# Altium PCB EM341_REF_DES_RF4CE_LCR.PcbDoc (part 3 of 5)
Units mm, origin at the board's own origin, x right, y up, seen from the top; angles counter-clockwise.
Board outline 218.38 x 83.13 mm, 2 copper layers (Top Layer, Carbon Ink Layer); 111 components, 91 nets, 369 pads, 80 vias.
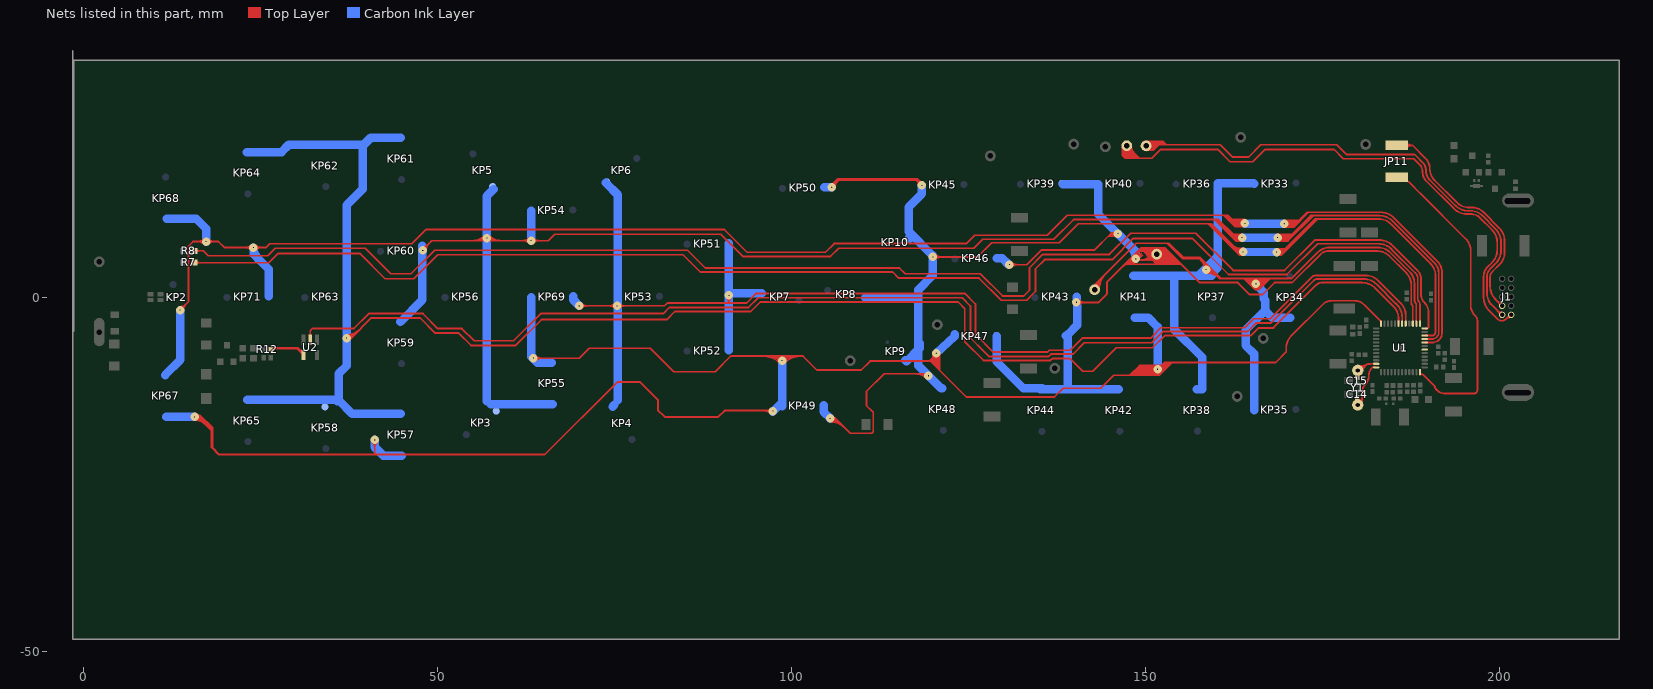
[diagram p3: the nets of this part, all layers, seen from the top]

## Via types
v1: diameter 1.2, hole 0, Top Layer to Carbon Ink Layer, 80 vias

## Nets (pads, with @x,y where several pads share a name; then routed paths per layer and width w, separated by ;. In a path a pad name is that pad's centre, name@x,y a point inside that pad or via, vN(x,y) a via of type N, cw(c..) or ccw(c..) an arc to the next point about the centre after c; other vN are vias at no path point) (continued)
NetR12_2: R12.2 U2.4 | length 20.1
  Top Layer w0.254: R12.2@26.35,-7.275 26.465,-7.16 30.28,-7.16 31.13,-8.01 U2.4@31.13,-8.29 ; R12.2@26.417,-7.403 26.527,-7.403 26.527,-7.623 26.85,-7.3 ; U2.4@30.81,-7.93 30.18,-7.3 26.85,-7.3 ; U2.4@30.931,-8.256 U2.4@30.95,-8.275 ; U2.4@31.023,-8.173 U2.4@31.05,-8.2 ; R12.2@26.557,-7.493 cw(c27.023,-7.959) 27.023,-7.3 ccw(c27.023,-7.959) R12.2@26.557,-7.493 ; R12.2@26.557,-7.493 cw(c27.361,-8.297) 27.361,-7.16 ccw(c27.361,-8.297) R12.2@26.557,-7.493 ; R12.2@26.557,-7.213 ccw(c26.767,-7.003) 26.767,-7.3 ; R12.2@26.557,-7.213 ccw(c26.767,-7.003) 26.767,-7.3 ; R12.2@26.557,-7.213 ccw(c26.767,-7.003) 26.767,-7.3 ; R12.2@26.557,-7.213 ccw(c26.767,-7.003) 26.767,-7.3 ; 26.85,-7.3 ccw(c26.85,-7.601) 26.589,-7.451 cw(c26.85,-7.601) 26.85,-7.3 ; R12.2@26.377,-7.313 cw(c26.748,-7.684) 26.748,-7.16 ccw(c26.748,-7.684) R12.2@26.377,-7.313 ; 30.399,-7.519 ccw(c30.751,-7.166) 30.985,-7.606 cw(c30.751,-7.166) 30.399,-7.519 ; 30.465,-7.345 ccw(c31.054,-6.756) 31.054,-7.589 cw(c31.054,-6.756) 30.465,-7.345 ; 30.641,-7.761 ccw(c30.919,-7.483) 31.104,-7.831 cw(c30.919,-7.483) 30.641,-7.761 ; U2.4@30.884,-8.004 ccw(c31.088,-7.801) 31.223,-8.055 cw(c31.088,-7.801) U2.4@30.884,-8.004
NRESET: JP11.1 U1.12 | length 43.7
  Top Layer w0.254: JP11.1@185.42,16.93 185.44,16.95 cw(c185.482,16.907) JP11.1@185.482,16.967 ; JP11.1@186.672,16.412 cw(c186.672,15.644) 187.215,16.187 188.777,14.625 ; U1.12@188.703,-10.6 188.703,-10.811 ccw(c188.769,-10.811) 188.722,-10.857 188.73,-10.865 cw(c188.73,-11.698) 189.319,-11.109 189.32,-11.11 ; 188.766,14.639 195.143,8.262 cw(c193.347,6.466) 195.887,6.466 195.887,5.201 ; 189.315,-11.111 190.787,-12.582 cw(c190.638,-12.731) 190.848,-12.731 ; 190.85,-12.73 ccw(c191.224,-12.73) 190.96,-12.995 191.109,-13.144 ccw(c192.283,-11.97) 192.283,-13.63 194.686,-13.63 ; 194.677,-13.633 196.335,-13.633 ccw(c196.335,-13.18) 196.655,-13.5 ccw(c196.183,-13.028) 196.85,-13.028 196.85,-3.902 ; 195.887,5.155 195.887,-1.183 ccw(c197.904,-1.183) 196.477,-2.61 cw(c195.578,-3.509) 196.85,-3.509 196.85,-4.09
NRESET_1: J1.8 JP11.2 | length 42.4
  Top Layer w0.254: JP11.2@185.42,21.43 187.655,21.43 189.486,19.599 ; JP11.2@185.542,21.452 cw(c185.542,19.592) JP11.2@186.857,20.907 ; 188.921,20.164 189.486,19.599 ; J1.8@200.315,-1.245 199.365,-0.295 cw(c201.161,1.501) 198.621,1.501 198.621,2.806 cw(c199.761,2.806) 198.955,3.613 199.996,4.654 ccw(c198.37,6.28) 200.67,6.28 200.67,7.927 ccw(c198.13,7.927) 199.926,9.723 197.633,12.017 ccw(c196.125,10.509) 196.125,12.641 195.692,12.641 cw(c195.692,15.181) 193.896,13.385 190.762,16.519 cw(c192.348,18.105) 190.105,18.105 ccw(c187.993,18.105) 189.486,19.599 ; 187.633,21.43 cw(c187.633,22.693) 186.74,21.8 ccw(c187.633,22.693) 187.633,21.43 ; 187.633,21.43 ccw(c187.633,20.167) 186.74,21.06 cw(c187.633,20.167) 187.633,21.43 ; 199.764,-0.694 cw(c199.212,-1.245) J1.8@199.992,-1.245 ; 199.764,-0.694 ccw(c200.315,-0.142) J1.8@200.315,-0.922 ; 199.764,-0.694 cw(c199.212,-1.245) J1.8@199.992,-1.245 ; 199.764,-0.694 ccw(c200.315,-0.142) J1.8@200.315,-0.922 ; 199.764,-0.694 ccw(c200.315,-0.142) J1.8@200.315,-0.922 ; 199.764,-0.694 cw(c199.212,-1.245) J1.8@199.992,-1.245
OSCA: C14.1 U1.48 Y1.1 | length 10.2
  Top Layer w0.254: C14.1@179.842,-14.16 cw(c179.561,-14.442) 179.959,-14.442 Y1.1@179.959,-15.226 ; Y1.1@180.069,-14.57 ccw(c180.176,-14.06) 180.626,-14.321 ccw(c181.334,-14.729) Y1.1@180.564,-15.003 ; U1.48@182.528,-9.925 182.089,-9.925 ccw(c182.089,-10.121) 181.95,-9.983 181.914,-10.018 ccw(c182.939,-11.043) 181.49,-11.043 181.49,-11.094 cw(c179.689,-11.094) 180.962,-12.367 ccw(c181.788,-13.193) 180.62,-13.193 180.62,-14.113 cw(c179.531,-14.113) 180.301,-14.884 Y1.1@179.959,-15.226 ; Y1.1@179.959,-15.226 179.959,-15.274 cw(c179.993,-15.24) 179.945,-15.24 Y1.1@179.959,-15.226 ; C14.1@179.735,-14.332 cw(c179.195,-14.873) 179.959,-14.873 ccw(c179.195,-14.873) C14.1@179.735,-14.332
OSCB: C15.1 U1.47 Y1.2 | length 7
  Top Layer w0.254: Y1.2@179.88,-10.709 cw(c179.987,-10.709) 179.911,-10.634 ccw(c178.389,-10.496) 179.917,-10.496 179.917,-10.348 180.096,-10.169 cw(c181.892,-11.965) 181.892,-9.425 U1.47@182.528,-9.425 ; Y1.2@179.905,-10.33 ccw(c179.857,-10.282) Y1.2@179.925,-10.282 ; Y1.2@180.038,-9.947 ccw(c180.234,-9.218) 180.611,-9.871 ; Y1.2@180.104,-9.702 ccw(c180.458,-8.38) 181.142,-9.565 ; Y1.2@180.343,-10.422 cw(c181.278,-10.582) 180.804,-9.76 ; Y1.2@180.593,-10.465 cw(c181.971,-10.7) 181.272,-9.49
PA0: KP3.2 KP5.2 KP54.1 KP55.1 KP56.1 KP59.1 KP60.1 | length 205.6
  Top Layer w0.254: v1@47.78,6.59 49.146,7.956 65.596,7.956 66.51,8.87 89.96,8.87 93.09,5.74 105.47,5.74 106.63,6.9 125.69,6.9 126.96,8.17 137.02,8.17 139.8,10.95 160.27,10.95 162.35,8.87 163.63,8.87 ; v1@47.9,7.063 ccw(c47.9,7.915) 48.503,7.313 ; v1@48.119,6.59 cw(c48.937,6.59) 48.359,7.169 ; v1@48.373,6.59 cw(c49.805,6.59) 48.792,7.602 ; 54.939,7.956 ccw(c54.939,10.341) v1@56.626,8.654 ; 55.553,7.956 ccw(c55.553,9.727) v1@56.805,8.475 ; 56.166,7.956 ccw(c56.166,9.114) v1@56.985,8.295 ; v1@56.935,8.295 ccw(c57.754,9.114) 57.754,7.956 ; v1@56.96,7.956 v1(56.96,8.32) ; v1@57.115,8.475 ccw(c58.367,9.727) 58.367,7.956 ; v1@57.294,8.654 ccw(c58.981,10.341) 58.981,7.956 ; 62.014,7.956 ccw(c62.014,9.146) v1@62.856,8.304 ; 62.082,7.956 cw(c62.082,6.862) v1@62.856,7.636 ; v1@63.524,7.636 cw(c64.298,6.862) 64.298,7.956 ; v1@63.524,8.304 ccw(c64.366,9.146) 64.366,7.956 ; 159.72,10.92 162.709,7.931 163.319,7.931 ; 160.09,10.83 162.679,8.241 ; 162.31,8.5 163.59,8.5 ; 162.34,8.65 163.62,8.65 ; 162.35,8.36 163.63,8.36 ; 162.67,8.2 163.64,8.2 ; 162.76,8.05 163.72,8.02
  Carbon Ink Layer w1.2: KP59.1@44.73,-3.51 47.826,-0.414 47.826,7.24 ; KP60.1@47.826,6.436 KP60.1@47.88,6.49 ; 56.936,-14.73 56.936,14.252 KP5.2@57.926,15.242 ; 57.494,-15.156 KP55.1@66.24,-15.156 ; v1@63.184,7.97 KP54.1@63.184,12.17
  other v1: 47.9,6.59 63.19,7.97
PA0_1: U1.21 | length 111.6
  Top Layer w0.254: v1@168.57,7.92 170.08,7.92 ; v1@168.58,8.87 170.64,8.87 ; v1@168.6,8.37 170.37,8.37 173.498,11.498 183.024,11.498 cw(c183.024,8.958) 184.82,10.754 190.827,4.746 cw(c189.541,3.46) 191.36,3.46 ; v1(168.6,8.4) 168.6,8.2 170.24,8.2 ; v1@168.806,8.676 170.676,8.676 ; v1@168.86,8.03 170.12,8.03 ; 170.47,8.48 169.25,8.48 ; 174.81,11.498 173.267,11.498 170.64,8.87 ; 175.24,11.498 173.658,11.498 170.08,7.92 ; U1.21@189.378,-5.925 190.436,-5.925 ccw(c190.436,-5.029) 191.07,-5.662 ccw(c190.357,-4.949) 191.366,-4.949 191.366,3.47 ; v1@168.755,8.245 cw(c169.794,7.206) 169.794,8.676 ccw(c169.794,7.206) v1@168.755,8.245 ; v1@168.755,8.245 cw(c169.322,7.678) 169.322,8.48 ccw(c169.322,7.678) v1@168.755,8.245 ; v1@168.755,8.555 ccw(c169.201,9.001) 169.201,8.37 cw(c169.201,9.001) v1@168.755,8.555 ; v1@168.755,8.555 ccw(c169.612,9.412) 169.612,8.2 cw(c169.612,9.412) v1@168.755,8.555 ; v1@168.934,8.066 cw(c170.407,6.593) 170.407,8.676 ccw(c170.407,6.593) v1@168.934,8.066 ; v1@168.934,8.066 cw(c169.935,7.065) 169.935,8.48 ccw(c169.935,7.065) v1@168.934,8.066 ; v1@168.934,8.066 cw(c169.669,7.331) 169.669,8.37 ccw(c169.669,7.331) v1@168.934,8.066 ; v1@168.934,8.066 cw(c169.259,7.741) 169.259,8.2 ccw(c169.259,7.741) v1@168.934,8.066 ; v1@168.934,8.734 ccw(c169.549,9.349) 169.549,8.48 cw(c169.549,9.349) v1@168.934,8.734 ; v1@168.934,8.734 ccw(c169.814,9.614) 169.814,8.37 cw(c169.814,9.614) v1@168.934,8.734 ; v1@168.934,8.734 ccw(c170.225,10.025) 170.225,8.2 cw(c170.225,10.025) v1@168.934,8.734 ; 169.25,8.48 cw(c169.25,8.741) 169.019,8.62 ccw(c169.25,8.741) 169.25,8.48 ; 169.25,8.48 ccw(c169.25,8.295) 169.067,8.324 cw(c169.25,8.295) 169.25,8.48 ; 170.08,7.92 cw(c170.08,9.073) 169.031,8.596 ccw(c170.08,9.073) 170.08,7.92 ; 170.12,8.03 cw(c170.12,9.349) 169.001,8.65 ccw(c170.12,9.349) 170.12,8.03 ; 170.64,8.87 ccw(c170.64,6.665) 168.96,8.094 cw(c170.64,6.665) 170.64,8.87 ; v1@168.38,8.587 cw(c168.992,8.067) 168.992,8.87 ccw(c168.992,8.067) v1@168.38,8.587 ; v1@168.568,8.386 ccw(c169.291,8.714) 169.291,7.92 cw(c169.291,8.714) v1@168.568,8.386 ; v1@168.57,8.381 ccw(c169.204,8.777) 169.204,8.03 cw(c169.204,8.777) v1@168.57,8.381 ; v1@168.573,8.423 cw(c169.541,7.6) 169.541,8.87 ccw(c169.541,7.6) v1@168.573,8.423 ; v1@168.575,8.425 cw(c169.181,7.819) 169.181,8.676 ccw(c169.181,7.819) v1@168.575,8.425 ; v1@168.767,8.258 cw(c170.09,7.132) 170.09,8.87 ccw(c170.09,7.132) v1@168.767,8.258 ; v1@168.786,8.516 ccw(c169.662,9.063) 169.662,8.03 cw(c169.662,9.063) v1@168.786,8.516 ; v1@168.799,8.491 ccw(c169.686,8.893) 169.686,7.92 cw(c169.686,8.893) v1@168.799,8.491
  Carbon Ink Layer w1.2: v1@163.6,8.396 v1@168.599,8.373
  other v1: 163.6,8.4
PA1: 
PA1_1: KP8.2 KP9.2 KP10.1 KP45.1 KP48.1 KP49.1 KP50.1 U1.22 | length 313.8
  Top Layer w0.254: v1(105.43,-17.14) 106.15,-17.14 ; v1@118.3,16.12 117.76,16.66 106.43,16.66 ; v1@118.394,15.68 117.588,16.489 106.65,16.507 v1(105.65,15.51) 105.65,15.88 106.43,16.66 ; v1(119.3,-11.12) 119.02,-10.84 113.05,-10.84 110.55,-13.34 110.55,-15.31 111.52,-16.28 111.52,-19 111.29,-19.23 108.24,-19.23 106.15,-17.14 ; v1(119.93,5.66) 126.21,5.66 128.22,7.67 137.75,7.67 140.44,10.36 159.23,10.36 162.78,6.81 ; v1@120.264,5.326 cw(c121.072,4.518) 121.072,5.66 cw(c121.072,6.802) v1@120.264,5.994 ; 158.82,10.36 163.28,5.9 v1@163.76,5.9 ; 159.045,10.305 163.33,6.02 163.33,5.9 ; 163.089,6.184 ccw(c163.75,6.844) v1@163.75,5.91 ; 163.129,6.184 ccw(c163.79,6.844) v1@163.79,5.91 ; v1@163.69,6.81 162.78,6.81 ; v1(163.74,6.37) 163.02,6.37 ; v1@163.78,6.63 162.94,6.63 ; v1@168.38,6.48 169.44,6.48 ; v1@168.46,5.89 169.11,5.89 174.255,11.035 ; v1(168.47,6.36) 169.36,6.36 ; v1@168.53,6.09 169.18,6.09 ; v1@168.57,6.81 169.69,6.81 ; v1@168.62,6.64 169.62,6.64 ; v1@168.63,6.26 169.36,6.26 ; 174.035,11.035 169.36,6.36 ; U1.22@189.378,-5.425 190.511,-5.425 ccw(c190.511,-5.103) 190.738,-5.331 ccw(c190.32,-4.913) 190.912,-4.913 190.912,2.335 ; 190.907,2.3 190.907,2.972 ccw(c188.367,2.972) 190.164,4.768 184.643,10.288 ccw(c182.847,8.492) 182.847,11.032 180.848,11.032 176.923,11.035 173.915,11.035 169.69,6.81 ; 106.15,-17.14 cw(c106.15,-16.829) 105.864,-16.952 ccw(c106.15,-16.829) 106.15,-17.14 ; 106.15,-17.14 ccw(c106.15,-17.451) 105.864,-17.328 cw(c106.15,-17.451) 106.15,-17.14 ; 106.43,16.66 ccw(c107.252,15.838) 106.113,15.605 cw(c107.252,15.838) 106.43,16.66 ; 106.459,16.316 cw(c105.653,17.125) 105.651,15.983 ccw(c105.653,17.125) 106.459,16.316 ; 106.459,16.316 ccw(c107.265,15.507) 106.123,15.509 cw(c107.265,15.507) 106.459,16.316 ; 162.78,6.81 cw(c162.78,6.322) 163.268,6.346 ccw(c162.78,6.322) 162.78,6.81 ; 162.94,6.63 cw(c162.94,6.3) 163.269,6.329 ccw(c162.94,6.3) 162.94,6.63 ; 163.02,6.37 cw(c163.02,6.059) 163.306,6.182 ccw(c163.02,6.059) 163.02,6.37 ; 163.02,6.37 ccw(c163.02,6.681) 163.306,6.558 cw(c163.02,6.681) 163.02,6.37 ; v1@163.74,6.081 cw(c163.74,7.629) 162.646,6.534 ccw(c163.74,7.629) v1@163.74,6.081 ; v1@163.74,6.081 cw(c163.74,7.218) 162.936,6.414 ccw(c163.74,7.218) v1@163.74,6.081 ; v1@163.74,6.335 cw(c163.74,8.496) 162.212,6.968 ccw(c163.74,8.496) v1@163.74,6.335 ; v1@163.74,6.335 cw(c163.74,8.085) 162.502,6.848 ccw(c163.74,8.085) v1@163.74,6.335 ; v1@163.74,6.589 cw(c163.74,9.363) 161.779,7.401 ccw(c163.74,9.363) v1@163.74,6.589 ; v1@163.74,6.589 cw(c163.74,8.953) 162.069,7.281 ccw(c163.74,8.953) v1@163.74,6.589 ; v1@163.74,6.843 cw(c163.74,10.23) 161.345,7.835 ccw(c163.74,10.23) v1@163.74,6.843 ; v1@163.74,6.843 cw(c163.74,9.82) 161.635,7.715 ccw(c163.74,9.82) v1@163.74,6.843 ; 169.36,6.26 cw(c169.36,6.765) 168.901,6.556 ccw(c169.36,6.765) 169.36,6.26 ; 169.36,6.26 ccw(c169.36,5.485) 168.807,6.028 cw(c169.36,5.485) 169.36,6.26 ; 169.36,6.36 cw(c169.36,6.961) 168.862,6.625 ccw(c169.36,6.961) 169.36,6.36 ; 169.36,6.36 ccw(c169.36,5.759) 168.862,6.095 cw(c169.36,5.759) 169.36,6.36 ; 169.44,6.48 ccw(c169.44,5.863) 168.891,6.144 cw(c169.44,5.863) 169.44,6.48 ; 169.62,6.64 ccw(c169.62,5.859) 168.904,6.171 cw(c169.62,5.859) 169.62,6.64 ; 169.69,6.81 ccw(c169.69,6.015) 168.925,6.231 cw(c169.69,6.015) 169.69,6.81 ; v1@105.406,-17.114 cw(c105.765,-17.5) 106.138,-17.128 ccw(c105.765,-17.5) v1@105.406,-17.114 ; v1@105.43,-17.613 cw(c105.43,-20.493) 107.467,-18.457 ccw(c105.43,-20.493) v1@105.43,-17.613 ; v1@105.43,-17.359 cw(c105.43,-19.626) 107.033,-18.023 ccw(c105.43,-19.626) v1@105.43,-17.359 ; v1@105.43,-17.105 cw(c105.43,-18.759) 106.599,-17.589 ccw(c105.43,-18.759) v1@105.43,-17.105 ; v1@105.43,-16.851 cw(c105.43,-17.892) 106.166,-17.156 ccw(c105.43,-17.892) v1@105.43,-16.851 ; v1@105.579,-17.3 cw(c105.945,-17.693) 106.324,-17.314 ccw(c105.945,-17.693) v1@105.579,-17.3 ; v1@105.752,-17.486 cw(c106.124,-17.886) 106.51,-17.5 ccw(c106.124,-17.886) v1@105.752,-17.486 ; v1@105.865,15.554 cw(c106.698,15.725) 106.096,16.326 ccw(c106.698,15.725) v1@105.865,15.554 ; 117.482,-10.84 cw(c117.482,-12.938) 118.966,-11.454 ccw(c117.482,-12.938) 117.482,-10.84 ; 117.637,16.439 ccw(c118.147,16.947) 118.296,16.243 cw(c118.147,16.947) 117.637,16.439 ; 117.658,16.418 cw(c117.02,15.782) 117.921,15.781 ccw(c117.02,15.782) 117.658,16.418 ; 117.982,16.438 cw(c117.484,15.94) 118.178,15.818 ccw(c117.484,15.94) 117.982,16.438 ; 118.007,16.413 ccw(c118.394,16.8) 118.394,16.253 cw(c118.394,16.8) 118.007,16.413 ; 118.095,-10.84 cw(c118.095,-12.325) 119.145,-11.275 ccw(c118.095,-12.325) 118.095,-10.84 ; 118.709,-10.84 cw(c118.709,-11.711) 119.325,-11.095 ccw(c118.709,-11.711) 118.709,-10.84 ; 163.047,6.81 cw(c163.047,6.335) 163.521,6.359 ccw(c163.047,6.335) 163.047,6.81 ; 163.314,6.81 cw(c163.314,6.349) 163.775,6.372 ccw(c163.314,6.349) 163.314,6.81 ; v1@168.436,6.37 cw(c169.019,6.205) 169.019,6.81 ccw(c169.019,6.205) v1@168.436,6.37 ; v1@168.671,6.273 cw(c169.232,6.028) 169.232,6.64 ccw(c169.232,6.028) v1@168.671,6.273 ; v1@168.681,6.3 cw(c169.354,6.11) 169.354,6.81 ccw(c169.354,6.11) v1@168.681,6.3 ; v1@168.804,6.694 ccw(c169.322,7.212) 169.322,6.48 cw(c169.322,7.212) v1@168.804,6.694
  Carbon Ink Layer w1.2: KP49.1@104.536,-15.28 104.5,-15.316 104.5,-16.21 v1@105.46,-17.17 ; KP50.1@104.586,15.48 105.58,15.48 105.59,15.49 v1(105.65,15.51) ; KP8.2@110.356,-0.086 117.824,-0.086 117.89,-0.02 ; KP9.2@116.035,-8.91 116.205,-9.08 116.21,-9.08 118.06,-7.23 118.06,-6.5 ; KP10.1@116.538,8.155 116.62,8.237 116.62,8.46 ; v1(118.394,15.78) 118.394,14.584 116.52,12.71 116.52,9.24 119.87,5.89 119.89,5.91 119.89,3.04 117.89,1.04 117.89,-9.7 121.104,-12.914 KP48.1@121.27,-12.914 ; 120.32,-12.13 120.344,-12.154 ; v1(163.74,6.37) v1@168.46,6.36
PA2: R8.1 U1.24 | length 200.3
  Top Layer w0.254: R8.1@15.65,6.53 16.91,6.53 17.62,5.82 25.98,5.82 27.06,6.9 39.76,6.9 43.36,3.3 46.24,3.3 49.56,6.62 85.28,6.62 87.8,4.1 115.21,4.1 116.01,3.3 126.63,3.3 129.78,0.15 132.76,0.15 133.58,0.97 133.58,4.15 135.45,6.02 144.86,6.02 147.86,9.02 157.07,9.02 162.32,3.77 169.59,3.77 173.869,8.049 183.003,8.049 cw(c183.003,5.509) 184.799,7.305 188.404,3.7 cw(c187.31,2.605) 188.857,2.605 188.857,0.386 ccw(c190.458,0.386) 189.326,-0.746 cw(c187.851,-2.222) 189.937,-2.222 189.937,-4.161 cw(c189.656,-4.161) 189.855,-4.36 cw(c189.698,-4.203) 189.698,-4.425 U1.24@189.378,-4.425 ; R8.1@15.857,6.323 cw(c16.355,5.825) 16.355,6.53 cw(c16.355,7.235) R8.1@15.857,6.737
PA2_1: 
PA3: R7.1 U1.25 | length 197.8
  Top Layer w0.254: R7.1@15.78,4.83 26.15,4.83 27.49,6.17 38.97,6.17 42.56,2.58 46.6,2.58 50,5.98 84.65,5.98 87.09,3.54 114.25,3.54 115.11,2.68 126.44,2.68 129.58,-0.46 133.17,-0.46 134.42,0.79 134.42,4 135.71,5.29 145.25,5.29 148.24,8.28 156.58,8.28 161.68,3.18 169.93,3.18 174.268,7.518 182.892,7.518 cw(c182.892,4.978) 184.688,6.774 188.066,3.396 cw(c187.251,2.581) 188.403,2.581 188.403,-0.279 ccw(c188.904,-0.279) 188.55,-0.633 cw(c188.18,-1.003) 188.703,-1.003 U1.25@188.703,-3.75 ; R7.1@15.857,4.673 cw(c16.234,4.296) 16.234,4.83 ; R7.1@15.857,5.087 ccw(c16.476,5.706) 16.476,4.83
PA3_1: 
PA4: KP33.2 KP34.1 KP35.1 KP36.2 KP37.1 KP38.1 KP41.1 pad.4 U1.26 | length 288.3
  Top Layer w0.254: pad.4@142.44,1.05 142.44,1.39 143.608,2.558 ; pad.4@142.9,0.94 142.9,1.85 148.66,7.61 ; pad.4@143.04,1.2 143.04,1.99 ; pad.4@143.26,1.34 143.26,2.03 ; pad.4@143.41,0.94 143.41,2.36 ; 149.81,7.61 148.66,7.61 ; 150.96,7.61 153.05,7.61 155.23,5.43 157.59,5.43 160.39,2.63 161.23,2.63 ; 163.82,2.63 165.37,1.08 ; 164.38,2.2 164.38,2.48 ; 164.6,1.97 164.6,2.48 ; 164.81,1.89 164.81,2.48 ; 164.94,1.66 164.94,2.48 ; v1@165.07,1.53 165.07,2.48 ; v1@165.24,1.42 165.24,2.48 ; v1@165.331,1.456 cw(c165.153,1.079) 165.57,1.079 ; v1@165.331,1.457 cw(c165.153,1.08) 165.57,1.08 ; v1@165.37,1.54 165.37,1.08 ; 165.371,1.09 cw(c165.744,1.064) 165.651,1.426 ccw(c165.744,1.064) 165.372,1.1 ; v1@165.455,1.417 cw(c165.393,1.046) 165.768,1.08 ; v1@165.455,1.451 cw(c165.393,1.08) 165.77,1.08 v1@165.77,1.5 ; v1@165.47,1.43 165.47,2.48 ; v1(165.533,1.884) 165.74,2.61 ; v1@165.57,1.6 165.57,1.08 ; v1@165.61,1.52 165.61,2.48 ; v1@165.85,1.41 165.85,2.48 ; 165.91,1.31 165.91,2.63 ; 166.05,1.24 166.05,1.46 ; 166.07,1.47 166.07,2.48 ; 166.2,1.41 166.2,2.48 ; 166.36,1.49 166.36,2.63 ; 166.48,1.74 166.48,2.48 ; 166.55,1.74 166.55,2.48 ; 166.66,1.877 166.66,2.48 ; 166.8,2 166.8,2.48 ; 166.92,2.2 166.92,2.48 ; 167.05,2.275 167.05,2.48 ; 167.56,2.63 166.01,1.08 165.37,1.08 ; 187.932,1.97 ccw(c185.719,1.97) 187.284,3.536 184.559,6.261 ccw(c182.762,4.465) 182.762,7.005 175.934,7.005 ccw(c175.934,4.683) 174.293,6.325 170.598,2.63 160.62,2.63 157.65,5.6 155.26,5.6 153.25,7.61 148.66,7.61 ; 187.949,1.97 187.949,-0.448 ccw(c188.56,-0.448) 188.128,-0.879 cw(c187.947,-1.061) 188.203,-1.061 U1.26@188.203,-3.75 ; 143.04,1.99 cw(c142.724,1.99) 142.739,1.674 ccw(c142.724,1.99) 143.04,1.99 ; 143.41,2.36 cw(c142.724,2.36) 142.748,1.675 ccw(c142.724,2.36) 143.41,2.36 ; 143.41,2.36 148.66,7.61 ; 143.608,2.558 ccw(c144.434,1.733) 143.356,1.284 cw(c144.434,1.733) 143.608,2.558 ; v1@158.52,3.651 cw(c158.52,1.046) 160.362,2.888 ccw(c158.52,1.046) v1@158.52,3.651 ; v1@158.52,3.651 cw(c158.52,1.601) 159.969,3.051 ccw(c158.52,1.601) v1@158.52,3.651 ; v1@158.52,3.905 cw(c158.52,1.913) 159.928,3.322 ccw(c158.52,1.913) v1@158.52,3.905 ; v1@158.52,3.905 cw(c158.52,2.469) 159.536,3.484 ccw(c158.52,2.469) v1@158.52,3.905 ; 163.999,2.48 cw(c163.999,1.318) 165.089,1.72 ccw(c163.999,1.318) 163.999,2.48 ; 163.999,2.48 167.37,2.48 ; 165.57,1.079 cw(c166.057,1.079) 165.791,1.488 ccw(c166.057,1.079) 165.57,1.079 ; 165.74,2.61 cw(c165.388,2.71) 165.451,2.35 ccw(c165.388,2.71) 165.74,2.61 ; 165.74,2.61 ccw(c166.092,2.51) 165.848,2.237 cw(c166.092,2.51) 165.74,2.61 ; 167.37,2.48 ccw(c167.37,0.841) 165.944,1.65 cw(c167.37,0.841) 167.37,2.48 ; pad.4@142.643,1.04 cw(c143.978,1.04) 143.034,1.984 ccw(c143.978,1.04) pad.4@142.643,1.04 ; pad.4@142.757,1.421 ccw(c142.733,2.097) 143.41,2.097 cw(c142.733,2.097) pad.4@142.757,1.421 ; pad.4@142.766,1.167 ccw(c142.742,1.834) 143.41,1.834 cw(c142.742,1.834) pad.4@142.766,1.167 ; pad.4@142.774,0.913 ccw(c142.752,1.571) 143.41,1.571 cw(c142.752,1.571) pad.4@142.774,0.913 ; pad.4@142.887,1.089 cw(c143.676,1.417) 143.072,2.022 ccw(c143.676,1.417) pad.4@142.887,1.089 ; pad.4@142.897,1.04 cw(c144.845,1.04) 143.468,2.418 ccw(c144.845,1.04) pad.4@142.897,1.04 ; 143.04,1.921 ccw(c143.651,1.921) 143.219,1.489 cw(c143.651,1.921) 143.04,1.921 ; pad.4@143.122,1.186 cw(c144.055,1.575) 143.34,2.29 ccw(c144.055,1.575) pad.4@143.122,1.186 ; pad.4@143.151,1.04 cw(c145.712,1.04) 143.901,2.851 ccw(c145.712,1.04) pad.4@143.151,1.04 ; pad.4@143.405,1.04 cw(c146.58,1.04) 144.335,3.285 ccw(c146.58,1.04) pad.4@143.405,1.04 ; 157.627,5.623 cw(c155.991,3.988) 158.301,3.88 ccw(c155.991,3.988) 157.627,5.623 ; 157.706,5.314 cw(c156.271,3.878) 158.301,3.871 ccw(c156.271,3.878) 157.706,5.314 ; 158.033,5.217 cw(c156.768,3.952) 158.555,3.868 ccw(c156.768,3.952) 158.033,5.217 ; 158.138,4.882 cw(c157.131,3.875) 158.555,3.87 ccw(c157.131,3.875) 158.138,4.882 ; 158.439,4.811 cw(c157.544,3.916) 158.809,3.856 ccw(c157.544,3.916) 158.439,4.811 ; v1@158.52,3.397 cw(c158.52,0.734) 160.403,2.617 ccw(c158.52,0.734) v1@158.52,3.397 ; v1@158.52,4.159 cw(c158.52,2.78) 159.495,3.755 ccw(c158.52,2.78) v1@158.52,4.159 ; v1@158.52,4.413 cw(c158.52,3.648) 159.061,4.189 ccw(c158.52,3.648) v1@158.52,4.413 ; 158.846,4.404 cw(c158.321,3.879) 159.062,3.845 ccw(c158.321,3.879) 158.846,4.404 ; 164.364,2.48 cw(c164.364,1.453) 165.328,1.808 ccw(c164.364,1.453) 164.364,2.48 ; 164.728,2.48 cw(c164.728,1.587) 165.566,1.896 ccw(c164.728,1.587) 164.728,2.48 ; v1@165.061,2.152 cw(c165.624,1.832) 165.624,2.48 ccw(c165.624,1.832) v1@165.061,2.152 ; 165.092,2.48 cw(c165.092,1.721) 165.804,1.984 ccw(c165.092,1.721) 165.092,2.48 ; v1@165.199,1.549 cw(c164.785,1.136) 165.37,1.136 ccw(c164.785,1.136) v1@165.199,1.549 ; v1@165.282,2.027 cw(c166.061,1.584) 166.061,2.48 ccw(c166.061,1.584) v1@165.282,2.027 ; 165.457,2.48 cw(c165.457,1.856) 166.043,2.072 ccw(c165.457,1.856) 165.457,2.48 ; v1@165.503,1.901 cw(c166.497,1.336) 166.497,2.48 ccw(c166.497,1.336) v1@165.503,1.901 ; v1@165.724,1.776 cw(c166.934,1.088) 166.934,2.48 ccw(c166.934,1.088) v1@165.724,1.776 ; 165.77,1.314 cw(c166.103,1.314) 165.868,1.549 ccw(c166.103,1.314) 165.77,1.314
  Carbon Ink Layer w1.2: KP41.1@148.23,2.98 KP37.1@159.28,2.98 ; 153.85,2.98 157.38,2.98 159.99,5.59 ; 154.02,2.91 154.02,-4.56 157.986,-8.526 157.986,-13.014 KP38.1@157.18,-13.014 ; KP37.1@159.18,3.18 160.187,4.187 KP36.2@160.187,16.07 165.223,16.07 KP33.2@165.323,15.97 ; KP35.1@165.284,-15.99 165.284,-8.004 164.1,-6.82 164.1,-4.67 166.94,-1.83 ; v1(165.533,1.884) 166.63,0.71 166.63,-0.22 166.89,-0.48 166.89,-1.95 167.886,-2.946 KP34.1@170.43,-2.946
  other v1: 158.52,3.87
PA4_1: 
PA4_2: J1.9 pad.3@147.31,21.37 | length 100.6
  Top Layer w0.254: pad.3@146.717,21.201 146.717,19.953 147.07,19.6 150.86,19.6 152.11,20.85 160.16,20.85 161.89,19.12 165.11,19.12 166.84,20.85 176.57,20.85 177.89,19.53 187.808,19.53 188.875,18.463 ccw(c187.984,17.572) 188.861,18.476 cw(c187.208,17.588) 189.085,17.588 ccw(c190.716,17.588) 189.562,16.434 193.529,12.468 ccw(c195.325,14.264) 195.325,11.724 195.88,11.724 cw(c195.88,9.887) 197.179,11.186 198.881,9.484 cw(c197.085,7.688) 199.625,7.688 199.625,6.667 cw(c197.085,6.667) 198.881,4.871 198.275,4.265 ccw(c199.657,2.883) 197.703,2.883 197.703,-0.07 ccw(c200.243,-0.07) 198.446,-1.866 199.69,-3.11 ; 146.937,19.853 pad.3@146.937,21.101 ; 147.157,19.763 pad.3@147.157,21.011 ; 147.166,19.857 148.414,19.857 ; pad.3@147.31,20.735 cw(c147.31,19.202) 148.394,20.286 cw(c149.478,21.37) pad.3@147.945,21.37 ; pad.3@147.31,20.989 cw(c147.31,20.069) 147.96,20.72 cw(c148.611,21.37) pad.3@147.691,21.37 ; pad.3@147.31,21.37 149.08,19.6 ; 147.407,19.773 pad.3@147.407,21.021 ; 147.424,20.505 148.306,19.623 ; 147.547,19.773 pad.3@147.547,21.021 ; 147.647,19.773 pad.3@147.647,21.021 ; 147.697,20.545 148.579,19.663 ; 147.787,19.753 pad.3@147.787,21.001 ; 147.857,20.605 148.739,19.723 ; 147.957,19.723 pad.3@147.957,20.971 ; 199.691,-3.108 199.712,-3.129 ccw(c200.233,-2.609) 200.233,-3.345 ccw(c200.233,-2.379) 200.915,-3.062 ; J1.9@201.552,-2.836 ccw(c201.471,-3.618) 200.915,-3.062 ; J1.9@201.585,-2.515 ccw(c201.585,-2.811) 201.376,-2.602 200.915,-3.062 ; 201.12,-2.857 ccw(c200.778,-2.515) J1.9@201.262,-2.515 ; 201.12,-2.857 ccw(c200.778,-2.515) J1.9@201.262,-2.515 ; 201.12,-2.857 ccw(c200.778,-2.515) J1.9@201.262,-2.515 ; 200.854,-3.124 cw(c201.545,-3.815) 201.575,-2.838 ccw(c201.545,-3.815) 200.854,-3.124
PA5: KP39.2 KP40.1 KP42.2 KP43.1 KP44.2 KP46.1 KP47.1 pad.3@151.54,6.06 U1.27 | length 284.5
  Top Layer w0.254: v1(130.74,4.57) 133.2,4.57 135.26,6.63 142.74,6.63 145.08,8.97 ; v1@131.074,4.236 cw(c131.882,3.428) 131.882,4.57 cw(c131.882,5.712) v1@131.074,4.904 ; v1@140.25,-0.75 143.34,-0.75 144.53,0.44 144.53,2.15 149.34,6.96 152.69,6.96 157.61,2.04 163,2.04 164.7,0.34 166.48,0.34 168.19,2.05 170.672,2.05 174.676,6.054 cw(c175.7,5.03) 175.7,6.478 ; v1@140.544,-1.064 cw(c141.304,-1.824) 141.304,-0.75 ; v1@140.544,-0.396 ccw(c141.4,0.46) 141.4,-0.75 ; v1@140.613,-1.053 cw(c141.26,-1.592) 141.26,-0.75 cw(c141.26,0.092) v1@140.613,-0.447 ; 144.79,8.6 v1@146.12,8.6 ; 144.92,8.75 v1@146.25,8.75 ; 144.94,8.84 v1@146.27,8.84 ; 145.013,8.834 cw(c145.013,7.693) v1@145.82,8.5 ; 145.08,9 ccw(c145.08,10.142) v1@145.887,9.334 ; 145.11,8.89 ccw(c145.11,10.032) v1@145.917,9.224 ; 145.12,9.05 cw(c145.12,7.908) v1@145.927,8.716 ; 147.336,4.736 cw(c148.407,3.666) v1@148.558,5.172 ; 147.38,4.63 154.959,4.63 ; 147.715,5.115 cw(c148.476,4.354) v1@148.584,5.425 ; 147.808,4.898 cw(c148.478,4.227) v1@148.561,5.172 ; 147.971,5.061 ccw(c147.641,5.39) v1@148.107,5.39 ; v1@148.109,5.348 cw(c147.243,5.272) 147.858,4.658 cw(c148.491,4.024) v1@148.549,4.918 ; v1@148.208,5.098 cw(c148.011,4.944) 148.188,4.768 cw(c148.549,4.406) v1@148.565,4.917 ; v1@148.549,5.374 cw(c149.071,5.641) 148.656,6.056 ; v1@148.58,5.863 ccw(c148.58,6.329) 148.909,5.999 ; v1@148.585,5.385 149.35,6.15 ; v1@148.685,5.582 ccw(c148.929,6.031) 149.29,5.67 ; v1@148.772,5.822 ccw(c148.982,6.297) 149.35,5.93 ; v1@148.775,5.49 cw(c149.398,5.808) 148.903,6.303 ; v1@148.806,5.805 ccw(c149.098,6.342) 149.53,5.91 ; 149,6.09 ccw(c149.233,5.857) v1@148.965,5.665 ; v1@149.001,5.605 cw(c149.725,5.975) 149.15,6.55 ; v1@149.053,5.39 cw(c149.64,5.39) 149.225,5.805 ; 149.2,6.46 152.55,6.46 ; 149.2,6.68 152.91,6.68 ; 149.22,6.55 152.57,6.55 ; 149.29,5.22 ccw(c149.29,7.038) pad.3@150.958,6.313 ; 149.3,6.78 152.65,6.78 ; 149.429,6.9 cw(c149.429,4.846) pad.3@151.21,5.87 ; 149.678,5.22 ccw(c149.678,6.87) pad.3@151.191,6.212 ; 149.71,6.47 153.06,6.47 ; 149.77,6.37 153.12,6.37 ; 149.868,6.9 cw(c149.868,5.099) pad.3@151.43,5.997 ; 149.92,6.2 153.27,6.2 ; 150.065,5.22 ccw(c150.065,6.701) pad.3@151.424,6.111 ; 150.1,6.06 153.45,6.06 ; 150.16,5.93 153.51,5.93 ; 150.25,5.81 153.6,5.81 ; 150.307,6.9 cw(c150.307,5.351) pad.3@151.65,6.123 ; 150.452,5.22 ccw(c150.452,6.533) pad.3@151.656,6.009 ; 150.5,5.65 153.85,5.65 ; 150.63,5.52 153.98,5.52 ; 150.747,6.9 cw(c150.747,5.604) pad.3@151.87,6.25 ; 150.79,5.39 154.14,5.39 ; 150.793,5.577 ccw(c151.45,6.002) 151.45,5.22 ; 150.84,5.22 ccw(c150.84,6.364) pad.3@151.889,5.908 ; 150.883,5.22 154.233,5.22 ; pad.3@151.007,5.715 ccw(c151.917,6.303) 151.917,5.22 ; 151.12,5.04 154.47,5.04 ; 151.186,6.9 cw(c151.186,5.856) pad.3@152.09,6.377 ; pad.3@151.22,5.853 ccw(c152.383,6.605) 152.383,5.22 ; 151.227,5.22 ccw(c151.227,6.196) pad.3@152.122,5.807 ; 151.27,4.85 154.62,4.85 ; pad.3@151.433,5.991 ccw(c152.85,6.907) 152.85,5.22 ; 151.615,5.22 ccw(c151.615,6.027) 152.355,5.705 ; 151.625,6.9 cw(c151.625,6.109) 152.311,6.503 ; pad.3@151.647,6.129 ccw(c153.317,7.208) 153.317,5.22 ; pad.3@151.86,6.267 ccw(c153.783,7.51) 153.783,5.22 ; pad.3@152.073,6.405 ccw(c154.25,7.812) 154.25,5.22 ; 175.643,6.492 182.708,6.492 cw(c182.708,4.131) 184.377,5.8 186.752,3.426 cw(c184.956,1.63) 187.496,1.63 187.496,-0.863 ccw(c187.869,-0.863) 187.605,-1.128 cw(c187.367,-1.365) 187.703,-1.365 U1.27@187.703,-3.75 ; v1@148.966,5.664 cw(c149.603,6.117) 149.05,6.67 ccw(c149.603,6.117) v1@148.966,5.664 ; 149.35,6.15 cw(c148.653,6.847) 148.604,5.862 ccw(c148.653,6.847) 149.35,6.15 ; 149.35,6.15 ccw(c150.068,5.432) 149.053,5.403 cw(c150.068,5.432) 149.35,6.15 ; 146.39,4.01 cw(c148.58,1.82) 148.58,4.917 ccw(c148.58,1.82) 146.39,4.01 ; 146.823,4.443 cw(c148.58,2.687) 148.58,5.171 ccw(c148.58,2.687) 146.823,4.443 ; 147.257,4.877 cw(c148.58,3.554) 148.58,5.425 ccw(c148.58,3.554) 147.257,4.877 ; 147.691,5.311 cw(c148.58,4.421) 148.58,5.679 ccw(c148.58,4.421) 147.691,5.311 ; v1@148.344,5.223 cw(c148.858,5.587) 148.412,6.032 ccw(c148.858,5.587) v1@148.344,5.223 ; v1@148.551,5.37 cw(c149.106,5.764) 148.625,6.245 ccw(c149.106,5.764) v1@148.551,5.37 ; v1@148.759,5.517 cw(c149.354,5.94) 148.837,6.457 ccw(c149.354,5.94) v1@148.759,5.517
  Carbon Ink Layer w1.2: KP47.1@128.92,-5.53 128.92,-9.11 132.72,-12.91 KP44.2@135.39,-12.91 ; KP46.1@128.956,5.51 129.7,5.51 v1@130.655,4.555 ; KP44.2@135.113,-13.053 KP42.2@146.2,-13.053 ; KP39.2@138.27,15.95 138.3,15.92 143.27,15.92 143.27,11.72 148.58,6.41 v1(148.58,5.39) ; 138.72,-5.44 139,-5.72 ; 139,-13.053 139,-5.28 140.325,-3.955 140.325,-1.653 ; v1@140.24,-0.73 KP43.1@140.24,0.07 ; 140.32,-1.696 v1@140.32,-0.88 ; v1(148.58,5.39) ccw(c146.118,5.39) 147.859,7.131 cw(c146.118,5.39) v1(148.58,5.39)
  other v1: 140.21,-0.73 146.07,8.97
PA5_1: 
PA5_2: J1.10 pad.3@150.04,21.35 | length 92
  Top Layer w0.254: pad.3@149.953,20.86 151.043,20.86 ; pad.3@149.973,20.723 151.063,20.723 151.86,21.52 ; pad.3@150.023,22.003 152.407,22.003 152.777,21.633 pad.3@150.743,21.633 ; pad.3@150.04,21.35 150.21,21.52 160.49,21.52 162.25,19.76 164.5,19.76 166.26,21.52 176.94,21.52 178.32,20.14 187.945,20.14 189.335,18.75 cw(c187.848,17.243) 189.345,18.74 ; pad.3@150.063,21 151.153,21 ; pad.3@150.153,21.09 151.243,21.09 ; pad.3@150.283,21.21 151.373,21.21 ; pad.3@150.309,21.081 cw(c151.37,20.02) 151.37,21.52 ; pad.3@150.403,21.32 151.493,21.32 ; pad.3@150.489,20.901 cw(c151.983,19.407) 151.983,21.52 ; pad.3@150.489,21.799 ccw(c151.163,22.473) 151.163,21.52 ; 150.683,21.783 152.337,21.783 152.6,21.52 ; 189.335,18.75 cw(c187.367,17.76) 189.57,17.76 ccw(c191.239,17.76) 190.059,16.58 193.708,12.931 ccw(c195.504,14.727) 195.504,12.187 195.88,12.187 cw(c195.88,9.918) 197.485,11.522 199.409,9.599 cw(c197.613,7.803) 200.153,7.803 200.153,6.515 cw(c197.678,6.515) 199.428,4.765 198.637,3.975 ccw(c199.773,2.839) 198.167,2.839 198.167,0.612 ccw(c200.707,0.612) 198.911,-1.184 J1.10@200.275,-2.548 ; 199.64,-1.912 ccw(c200.315,-1.237) J1.10@200.315,-2.192 ; 199.64,-1.912 ccw(c200.315,-1.237) J1.10@200.315,-2.192 ; 199.64,-1.912 ccw(c200.315,-1.237) J1.10@200.315,-2.192 ; 199.815,-2.087 cw(c199.387,-2.515) J1.10@199.992,-2.515 ; 199.815,-2.087 cw(c199.387,-2.515) J1.10@199.992,-2.515 ; 199.815,-2.087 cw(c199.387,-2.515) J1.10@199.992,-2.515
PA6: KP4.1 KP6.1 KP7.1 KP51.1 KP52.1 KP53.2 KP69.1 U1.29 | length 196.3
  Top Layer w0.254: v1(69.99,-1.24) 82.03,-1.24 82.42,-0.85 93.61,-0.85 94.97,0.51 124.45,0.51 125.95,-0.99 125.95,-5.25 128.47,-7.77 136.116,-7.77 136.38,-7.506 139.314,-7.506 141.03,-5.79 150.67,-5.79 152.13,-4.33 163.98,-4.33 165.26,-3.05 167.575,-3.05 173.441,2.816 cw(c174.019,2.239) 174.019,3.056 181.032,3.056 cw(c181.032,0.516) 182.828,2.312 185.959,-0.819 cw(c184.163,-2.616) 186.703,-2.616 U1.29@186.703,-3.75 ; v1@70.324,-1.574 cw(c71.132,-2.382) 71.132,-1.24 cw(c71.132,-0.098) v1@70.324,-0.906 ; v1@75.006,-1.574 ccw(c74.198,-2.382) 74.198,-1.24 ccw(c74.198,-0.098) v1@75.006,-0.906 ; v1@75.674,-1.574 cw(c76.482,-2.382) 76.482,-1.24 cw(c76.482,-0.098) v1@75.674,-0.906 ; v1(91.13,0.23) 91.13,-0.84 ; 91.13,-0.84 cw(c92.104,-0.84) 91.448,-0.12 ccw(c92.104,-0.84) 91.13,-0.84 ; 91.13,-0.84 ccw(c90.156,-0.84) 90.812,-0.12 cw(c90.156,-0.84) 91.13,-0.84
  Carbon Ink Layer w1.2: KP69.1@69.136,0.1 69.136,-0.386 v1(69.99,-1.24) ; KP6.1@73.756,16.12 75.423,14.454 75.423,-14.597 ; KP4.1@74.729,-15.461 KP4.1@74.96,-15.229 ; 91.116,-1.04 91.126,-1.05 ; KP52.1@91.126,-7.5 KP51.1@91.126,7.59 ; v1@91.126,0.48 91.192,0.545 KP7.1@95.739,0.545 ; v1(91.13,0.23) cw(c91.892,-0.532) 91.892,0.545 ccw(c91.892,-0.532) v1(91.13,0.23)
  other v1: 75.34,-1.24
PA7: U1.18
PB0: KP41.2 KP47.2 KP49.2 KP55.2 KP57.2 KP67.2 KP69.2 U1.36 | length 507.9
  Top Layer w0.254: v1@15.69,-17.03 16.23,-17.03 18.06,-18.86 18.06,-21.25 19.04,-22.23 65.12,-22.23 75.348,-12.002 78.592,-12.002 81.1,-14.51 81.1,-15.97 82.06,-16.93 89.62,-16.93 90.52,-16.03 97.27,-16.03 v1(97.34,-16.1) ; v1@15.96,-16.68 16.44,-16.68 ; v1@16.15,-16.87 16.38,-16.87 ; 18.22,-18.71 16.38,-16.87 ; 19.14,-22.23 18.22,-21.31 18.22,-18.46 16.44,-16.68 ; 41.11,-22.23 v1(41.11,-20.16) ; v1(63.51,-8.63) 69.99,-8.63 71.38,-7.24 80.02,-7.24 83.33,-10.55 89.19,-10.55 91.41,-8.33 101.57,-8.33 103.54,-10.3 109.81,-10.3 111.06,-9.05 120.87,-9.05 ; v1@63.844,-8.964 cw(c64.652,-9.772) 64.652,-8.63 cw(c64.652,-7.488) v1@63.844,-8.296 ; 119.41,-9.05 119.95,-8.51 v1@119.95,-7.9 ; 119.6,-9.05 124.666,-14.116 137.094,-14.116 138.33,-12.88 143.62,-12.88 145.47,-11.03 151.9,-11.03 153.68,-9.25 ; 119.613,-8.847 120.857,-8.847 ; 119.88,-8.847 119.88,-8.81 120.1,-8.59 v1@120.1,-8.19 ; 120.02,-9.33 v1@120.02,-8.34 ; 120.16,-9.53 120.16,-8.54 ; 120.2,-8.847 v1@120.2,-8.29 ; 120.34,-9.69 120.34,-8.7 ; 120.41,-9.02 v1(120.41,-7.93) ; 120.44,-9.72 120.44,-8.73 ; 120.56,-9.8 120.56,-8.81 ; 120.6,-8.847 v1@120.6,-8.32 ; 120.7,-9.95 120.7,-8.96 ; 120.75,-8.847 v1@120.75,-8.17 ; 120.87,-10.29 v1@120.87,-7.98 ; 147.76,-11.03 149.12,-9.67 153.03,-9.67 ; 147.98,-11.03 149.34,-9.67 ; 148.883,-10.517 v1@152.057,-10.517 ; 149.027,-10.373 v1@152.013,-10.373 ; 149.09,-9.88 152.83,-9.88 ; 152.18,-9.67 152.6,-9.25 168.31,-9.25 169.823,-7.738 169.823,-7.34 ; 152.49,-9.52 152.96,-9.52 153.12,-9.36 153.34,-9.36 153.03,-9.67 ; 152.6,-9.39 152.95,-9.39 ; 169.823,-7.257 cw(c172.363,-7.257) 170.566,-5.461 174.947,-1.08 cw(c176.288,-2.42) 176.288,-0.525 ; 176.294,-0.525 179.46,-0.525 cw(c179.46,-2.456) 180.826,-1.091 183.16,-3.425 cw(c183.13,-3.455) U1.36@183.172,-3.455 ; U1.36@183.203,-3.75 U1.36@183.203,-3.478 ; v1@15.68,-17.393 cw(c15.68,-20.346) 17.768,-18.258 ccw(c15.68,-20.346) v1@15.68,-17.393 ; v1@15.68,-17.393 cw(c15.68,-19.597) 17.239,-18.039 ccw(c15.68,-19.597) v1@15.68,-17.393 ; v1@15.68,-17.139 cw(c15.68,-19.478) 17.334,-17.824 ccw(c15.68,-19.478) v1@15.68,-17.139 ; v1@15.68,-17.139 cw(c15.68,-18.73) 16.805,-17.605 ccw(c15.68,-18.73) v1@15.68,-17.139 ; v1@15.68,-16.885 cw(c15.68,-18.611) 16.901,-17.391 ccw(c15.68,-18.611) v1@15.68,-16.885 ; v1@15.68,-16.885 cw(c15.68,-17.863) 16.371,-17.171 ccw(c15.68,-17.863) v1@15.68,-16.885 ; 16.38,-16.87 cw(c16.38,-16.552) 16.099,-16.7 ccw(c16.38,-16.552) 16.38,-16.87 ; 16.38,-16.87 ccw(c16.38,-17.127) 16.134,-17.054 cw(c16.38,-17.127) 16.38,-16.87 ; 16.44,-16.68 ccw(c16.44,-16.969) 16.152,-16.95 cw(c16.44,-16.969) 16.44,-16.68 ; 41.11,-21.302 cw(c42.252,-21.302) 41.444,-20.494 ccw(c42.252,-21.302) 41.11,-21.302 ; 41.11,-21.302 ccw(c39.968,-21.302) 40.776,-20.494 cw(c39.968,-21.302) 41.11,-21.302 ; 120.41,-9.02 cw(c121.429,-9.02) 120.733,-8.275 ccw(c121.429,-9.02) 120.41,-9.02 ; 120.41,-9.02 ccw(c119.391,-9.02) 120.087,-8.275 cw(c119.391,-9.02) 120.41,-9.02 ; v1@151.326,-10.524 ccw(c149.263,-12.587) 149.263,-9.67 cw(c149.263,-12.587) v1@151.326,-10.524 ; v1@151.326,-10.524 ccw(c149.77,-12.08) 149.77,-9.88 cw(c149.77,-12.08) v1@151.326,-10.524 ; v1@151.326,-10.524 ccw(c150.084,-11.766) 150.084,-10.01 cw(c150.084,-11.766) v1@151.326,-10.524 ; v1@151.326,-10.524 ccw(c150.542,-11.308) 150.542,-10.2 cw(c150.542,-11.308) v1@151.326,-10.524 ; v1@151.326,-10.524 ccw(c150.959,-10.891) 150.959,-10.373 cw(c150.959,-10.891) v1@151.326,-10.524 ; v1@151.326,-9.856 cw(c150.953,-9.483) 150.953,-10.01 ccw(c150.953,-9.483) v1@151.326,-9.856 ; v1@151.326,-9.856 cw(c150.494,-9.024) 150.494,-10.2 ccw(c150.494,-9.024) v1@151.326,-9.856 ; v1@151.326,-9.856 cw(c150.077,-8.607) 150.077,-10.373 ccw(c150.077,-8.607) v1@151.326,-9.856 ; v1@151.326,-9.856 cw(c149.729,-8.259) 149.729,-10.517 ccw(c149.729,-8.259) v1@151.326,-9.856 ; v1@151.326,-9.856 cw(c149.214,-7.744) 149.214,-10.73 ccw(c149.214,-7.744) v1@151.326,-9.856 ; v1@151.326,-9.856 cw(c148.925,-7.455) 148.925,-10.85 ccw(c148.925,-7.455) v1@151.326,-9.856 ; v1@151.505,-10.345 ccw(c149.876,-11.974) 149.876,-9.67 cw(c149.876,-11.974) v1@151.505,-10.345 ; v1@151.505,-10.345 ccw(c150.383,-11.467) 150.383,-9.88 cw(c150.383,-11.467) v1@151.505,-10.345 ; v1@151.505,-10.345 ccw(c150.697,-11.153) 150.697,-10.01 cw(c150.697,-11.153) v1@151.505,-10.345 ; v1@151.505,-10.035 cw(c150.69,-9.22) 150.69,-10.373 ccw(c150.69,-9.22) v1@151.505,-10.035 ; v1@151.505,-10.035 cw(c150.342,-8.872) 150.342,-10.517 ccw(c150.342,-8.872) v1@151.505,-10.035 ; v1@151.505,-10.035 cw(c149.828,-8.358) 149.828,-10.73 ccw(c149.828,-8.358) v1@151.505,-10.035 ; v1@151.505,-10.035 cw(c149.538,-8.068) 149.538,-10.85 ccw(c149.538,-8.068) v1@151.505,-10.035 ; v1@151.685,-10.215 cw(c150.955,-9.485) 150.955,-10.517 ccw(c150.955,-9.485) v1@151.685,-10.215 ; v1@151.685,-10.215 cw(c150.441,-8.971) 150.441,-10.73 ccw(c150.441,-8.971) v1@151.685,-10.215 ; v1@151.685,-10.215 cw(c150.151,-8.681) 150.151,-10.85 ccw(c150.151,-8.681) v1@151.685,-10.215 ; v1@151.685,-10.165 ccw(c150.489,-11.361) 150.489,-9.67 cw(c150.489,-11.361) v1@151.685,-10.165 ; v1@151.685,-10.165 ccw(c150.996,-10.854) 150.996,-9.88 cw(c150.996,-10.854) v1@151.685,-10.165 ; v1@151.864,-10.394 cw(c151.054,-9.584) 151.054,-10.73 ccw(c151.054,-9.584) v1@151.864,-10.394 ; v1@151.864,-10.394 cw(c150.764,-9.294) 150.764,-10.85 ccw(c150.764,-9.294) v1@151.864,-10.394 ; v1@152.11,-10.337 cw(c153.03,-10.639) 153.03,-9.67 ; v1@152.109,-10.338 cw(c152.3,-10.401) 152.3,-10.2 ; v1@152.109,-10.338 cw(c152.3,-10.401) 152.3,-10.2 ; v1@152.11,-10.337 cw(c153.03,-10.639) 153.03,-9.67 ; 152.3,-10.2 cw(c152.3,-10.008) 152.115,-10.06 ccw(c152.3,-10.008) 152.3,-10.2 ; 152.3,-10.2 149.2,-10.2 148.67,-10.73 151.77,-10.73 152.49,-10.01 ; 152.49,-10.01 ccw(c152.49,-10.391) 152.12,-10.301 cw(c152.49,-10.391) 152.49,-10.01 ; 152.49,-10.01 149.129,-10.01 148.289,-10.85 151.86,-10.85 152.83,-9.88 ; 152.83,-9.88 ccw(c152.83,-10.673) 152.097,-10.37 cw(c152.83,-10.673) 152.83,-9.88 ; v1@15.68,-16.631 cw(c15.68,-17.744) 16.467,-16.957 ccw(c15.68,-17.744) v1@15.68,-16.631 ; v1@16.014,-16.586 ccw(c16.243,-16.357) 16.243,-16.68 cw(c16.243,-16.357) v1@16.014,-16.586 ; 95.939,-8.33 cw(c95.939,-11.691) 98.316,-9.314 ccw(c95.939,-11.691) 95.939,-8.33 ; 96.029,-16.03 cw(c96.029,-17.411) 97.006,-16.434 ccw(c96.029,-17.411) 96.029,-16.03 ; 96.367,-16.03 ccw(c96.367,-15.127) 97.006,-15.766 cw(c96.367,-15.127) 96.367,-16.03 ; 96.552,-8.33 cw(c96.552,-11.078) 98.495,-9.135 ccw(c96.552,-11.078) 96.552,-8.33 ; 96.642,-16.03 cw(c96.642,-16.798) 97.185,-16.255 ccw(c96.642,-16.798) 96.642,-16.03 ; 97.165,-8.33 cw(c97.165,-10.465) 98.675,-8.955 ccw(c97.165,-10.465) 97.165,-8.33 ; 97.778,-8.33 cw(c97.778,-9.852) 98.854,-8.776 ccw(c97.778,-9.852) 97.778,-8.33 ; 98.086,-8.416 cw(c98.295,-8.625) 98.295,-8.33 ccw(c98.295,-8.625) 98.086,-8.416 ; v1@98.266,-8.596 cw(c98.908,-9.238) 98.908,-8.33 ccw(c98.908,-9.238) v1@98.266,-8.596 ; 98.392,-8.33 cw(c98.392,-9.238) 99.034,-8.596 ccw(c98.392,-9.238) 98.392,-8.33 ; v1@98.446,-8.776 cw(c99.522,-9.852) 99.522,-8.33 ccw(c99.522,-9.852) v1@98.446,-8.776 ; v1@98.625,-8.955 cw(c100.135,-10.465) 100.135,-8.33 ccw(c100.135,-10.465) v1@98.625,-8.955 ; v1@98.805,-9.135 cw(c100.748,-11.078) 100.748,-8.33 ccw(c100.748,-11.078) v1@98.805,-9.135 ; v1@98.984,-9.314 cw(c101.361,-11.691) 101.361,-8.33 ccw(c101.361,-11.691) v1@98.984,-9.314 ; 99.005,-8.33 cw(c99.005,-8.625) 99.214,-8.416 ccw(c99.005,-8.625) 99.005,-8.33 ; v1@120.076,-8.264 cw(c119.775,-8.565) 120.2,-8.565 ccw(c119.775,-8.565) v1@120.076,-8.264 ; 120.2,-8.871 cw(c120.717,-8.871) 120.557,-8.38 ccw(c120.717,-8.871) 120.2,-8.871 ; 120.2,-8.521 cw(c120.603,-8.521) 120.478,-8.138 ccw(c120.603,-8.521) 120.2,-8.521 ; v1@120.253,-8.376 cw(c120.08,-8.867) 120.6,-8.867 ccw(c120.08,-8.867) v1@120.253,-8.376 ; v1@120.318,-8.394 cw(c120.183,-9.067) 120.87,-9.067 ccw(c120.183,-9.067) v1@120.318,-8.394 ; v1@120.323,-8.395 cw(c120.228,-8.908) 120.75,-8.908 ccw(c120.228,-8.908) v1@120.323,-8.395 ; v1@120.337,-8.137 cw(c120.206,-8.508) 120.6,-8.508 ccw(c120.206,-8.508) v1@120.337,-8.137 ; v1@120.367,-8.145 cw(c120.245,-8.758) 120.87,-8.758 ccw(c120.245,-8.758) v1@120.367,-8.145 ; v1@120.37,-8.145 cw(c120.285,-8.603) 120.75,-8.603 ccw(c120.285,-8.603) v1@120.37,-8.145 ; v1@120.417,-7.896 cw(c120.307,-8.448) 120.87,-8.448 ccw(c120.307,-8.448) v1@120.417,-7.896 ; 120.6,-8.613 cw(c121.093,-8.613) 120.744,-8.264 ccw(c121.093,-8.613) 120.6,-8.613 ; 151.102,-9.67 cw(c151.102,-10.748) 151.864,-9.986 ccw(c151.102,-10.748) 151.102,-9.67 ; 151.378,-10.85 ccw(c151.378,-9.908) 152.044,-10.574 cw(c151.378,-9.908) 151.378,-10.85 ; v1@151.385,-10.1 cw(c151.979,-10.294) 151.979,-9.67 ccw(c151.979,-10.294) v1@151.385,-10.1 ; v1@151.627,-10.179 cw(c152.329,-10.409) 152.329,-9.67 ccw(c152.329,-10.409) v1@151.627,-10.179 ; v1@151.862,-10.274 cw(c152.45,-10.516) 152.45,-9.88 ccw(c152.45,-10.516) v1@151.862,-10.274 ; v1@151.868,-10.258 cw(c152.68,-10.524) 152.68,-9.67 ccw(c152.68,-10.524) v1@151.868,-10.258 ; v1@151.994,-9.856 ccw(c152.367,-9.483) 152.367,-10.01 cw(c152.367,-9.483) v1@151.994,-9.856
  Carbon Ink Layer w1.2: KP67.2@11.64,-16.917 v1@15.68,-16.917 ; v1@41.12,-20.15 41.12,-21.21 42.327,-22.417 KP57.2@44.9,-22.417 ; KP69.2@63.233,-0.03 63.233,-8.423 64.063,-9.253 KP55.2@66.11,-9.253 ; v1@63.43,-8.63 v1@63.43,-8.4 ; v1(97.34,-16.1) 97.34,-16.17 98.633,-14.877 ; KP49.2@98.633,-15.41 v1@98.633,-8.85 ; 98.633,-9.753 98.63,-9.75 98.633,-9.636 v1(98.65,-8.98) ; v1(120.41,-7.93) KP47.2@122.993,-5.57 KP47.2@122.993,-5.277 ; KP41.2@148.41,-2.907 150.347,-2.907 151.66,-4.22 v1(151.66,-10.19)
  other v1: 15.68,-16.92
PB1: U1.30 U2.2 | length 175.7
  Top Layer w0.254: U2.2@32.004,-5.93 32.004,-4.736 32.32,-4.42 38.19,-4.42 40.27,-2.34 47.93,-2.34 50.04,-4.45 53.43,-4.45 55.16,-6.18 60.71,-6.18 64.55,-2.34 81.87,-2.34 82.73,-1.48 93.88,-1.48 95.26,-0.1 124.06,-0.1 125.24,-1.28 125.24,-5.78 127.138,-7.678 127.84,-8.38 136.307,-8.38 136.627,-8.06 139.72,-8.06 141.33,-6.45 150.85,-6.45 152.42,-4.88 164.36,-4.88 165.59,-3.65 167.725,-3.65 173.71,2.335 cw(c174.224,1.821) 174.224,2.548 180.792,2.548 cw(c180.792,0.008) 182.588,1.804 185.315,-0.923 185.459,-1.067 cw(c183.663,-2.863) 186.203,-2.863 U1.30@186.203,-3.75 ; 32.004,-5.23 cw(c31.647,-5.23) 31.899,-5.482 ccw(c31.647,-5.23) 32.004,-5.23 ; 32.004,-5.23 ccw(c32.361,-5.23) 32.109,-5.482 cw(c32.361,-5.23) 32.004,-5.23
PB2: KP57.1 KP58.1 KP61.1 KP62.1 KP63.1 KP64.1 KP65.1 U1.31 | length 264.3
  Top Layer w0.254: v1(37.14,-5.8) 37.79,-5.8 ; U1.31@185.703,-3.75 185.703,-3.103 ccw(c183.163,-3.103) 184.959,-1.307 182.357,1.296 ccw(c180.561,-0.5) 180.561,2.04 174.851,2.04 ccw(c174.851,1.989) 174.815,2.025 ccw(c174.815,0.993) 174.085,1.723 168.013,-4.35 165.92,-4.35 164.82,-5.45 152.67,-5.45 150.95,-7.17 145.8,-7.17 142.49,-10.48 141.11,-10.48 139.32,-8.69 136.78,-8.69 136.53,-8.94 127.08,-8.94 124.43,-6.29 124.43,-1.63 123.5,-0.7 95.56,-0.7 94.22,-2.04 83.48,-2.04 82.33,-3.19 64.66,-3.19 61.02,-6.83 54.71,-6.83 52.97,-5.09 49.65,-5.09 47.51,-2.95 40.64,-2.95 37.79,-5.8 ; 37.79,-5.8 cw(c37.79,-5.59) 37.59,-5.655 ccw(c37.79,-5.59) 37.79,-5.8 ; 37.79,-5.8 ccw(c37.79,-6.01) 37.59,-5.945 cw(c37.79,-6.01) 37.79,-5.8 ; v1@37.14,-6.089 ccw(c37.14,-5.217) 37.756,-5.834 cw(c37.14,-5.217) v1@37.14,-6.089 ; v1@37.14,-5.835 ccw(c37.14,-4.35) 38.19,-5.4 cw(c37.14,-4.35) v1@37.14,-5.835 ; v1@37.14,-5.581 ccw(c37.14,-3.483) 38.623,-4.967 cw(c37.14,-3.483) v1@37.14,-5.581 ; v1@37.14,-5.327 ccw(c37.14,-2.616) 39.057,-4.533 cw(c37.14,-2.616) v1@37.14,-5.327
  Carbon Ink Layer w1.2: KP64.1@23.07,20.476 27.956,20.476 28.976,21.496 39.556,21.496 40.546,22.486 KP61.1@44.77,22.486 ; KP65.1@23.08,-14.514 35.934,-14.514 35.975,-14.555 37.934,-16.514 KP57.1@44.77,-16.514 ; 35.8,-14.73 36.02,-14.51 36.02,-10.84 37.136,-9.724 37.136,12.956 39.42,15.24 39.42,21.496 ; 37.136,-2.93 37.14,-2.934
PB4: KP2.1 KP67.1 KP68.1 KP71.1 | length 211.7
  Top Layer w0.254: v1(13.64,-1.83) 14.81,-0.66 14.81,7.19 15.47,7.85 16.172,7.85 ccw(c16.172,8.958) v1@16.956,8.174 ; 16.124,7.85 cw(c16.124,6.674) v1@16.956,7.506 ; v1(17.29,7.84) 19.03,7.84 19.86,7.01 25.78,7.01 26.3,7.53 46.33,7.53 48.32,9.52 90.5,9.52 93.68,6.34 104.77,6.34 105.98,7.55 124.66,7.55 125.85,8.74 136.07,8.74 138.89,11.56 161.58,11.56 162.2,10.94 163.247,10.94 ; v1@17.624,7.506 cw(c18.432,6.698) 18.432,7.84 cw(c18.432,8.982) v1@17.624,8.174 ; 22.776,7.01 cw(c22.776,5.766) v1@23.656,6.646 ; 22.921,7.01 ccw(c22.921,8.049) v1@23.656,7.314 ; 23.389,7.01 cw(c23.389,6.379) v1@23.835,6.825 ; v1@24.145,6.825 cw(c24.591,6.379) 24.591,7.01 ; v1@24.324,6.646 cw(c25.204,5.766) 25.204,7.01 ; v1@24.324,7.314 ccw(c25.059,8.049) 25.059,7.01 ; 160.97,11.56 162.13,10.4 164,10.4 ; 161.31,11.42 161.93,10.8 ; 161.49,11.45 162.11,10.83 ; 161.879,10.861 162.34,10.4 ; 162.19,10.64 163.97,10.64 ; 162.289,10.779 163.166,10.779 ; 163.049,10.939 163.926,10.939 ; 163.247,10.82 164.01,10.82 ; 14.447,-1.023 cw(c13.64,-0.215) 13.64,-1.357 ccw(c13.64,-0.215) 14.447,-1.023 ; 14.447,-1.023 ccw(c15.255,-1.83) 14.113,-1.83 cw(c15.255,-1.83) 14.447,-1.023
  Carbon Ink Layer w1.2: KP67.1@11.51,-11.014 13.64,-8.884 v1(13.64,-1.83) ; KP68.1@11.72,11.034 15.936,11.034 17.3,9.67 v1@17.3,7.85 ; v1(17.29,7.84) v1@17.29,7.9 ; v1(23.99,6.98) ccw(c26.163,6.98) 24.626,5.444 ; v1@24,6.98 24,6.07 26.114,3.956 26.114,3.466 ; KP71.1@26.136,0.09 26.136,3.466
PB4_1: U1.20 | length 102.2
  Top Layer w0.254: 161.856,10.674 162.55,9.98 v1@164.079,9.98 ; 162.38,10.32 v1@164.25,10.32 ; 162.41,10.18 v1@164.28,10.18 ; v1@169.54,10.8 171.59,10.8 ; v1@169.57,9.88 170.88,9.88 ; v1@169.63,10.17 171.1,10.17 ; v1@169.79,10.51 171.35,10.51 ; v1@169.82,10.04 170.89,10.04 ; v1@169.83,10.66 171.52,10.66 ; v1@169.94,10.36 171.36,10.36 ; 172.968,11.967 170.88,9.88 ; 184.992,11.224 ccw(c183.196,9.427) 183.196,11.967 172.758,11.967 171.59,10.8 ; 185.01,11.202 185.015,11.202 191.181,5.037 cw(c189.639,3.495) 191.82,3.495 191.82,-5.134 cw(c190.613,-5.134) 191.466,-5.987 cw(c190.41,-4.931) 190.41,-6.425 U1.20@189.378,-6.425 ; v1@169.705,10.195 cw(c170.827,9.073) 170.827,10.66 ccw(c170.827,9.073) v1@169.705,10.195 ; v1@169.705,10.195 cw(c170.465,9.435) 170.465,10.51 ccw(c170.465,9.435) v1@169.705,10.195 ; v1@169.884,10.016 cw(c171.44,8.46) 171.44,10.66 ccw(c171.44,8.46) v1@169.884,10.016 ; v1@169.884,10.016 cw(c170.716,9.184) 170.716,10.36 ccw(c170.716,9.184) v1@169.884,10.016 ; v1@169.884,10.016 cw(c171.078,8.822) 171.078,10.51 ccw(c171.078,8.822) v1@169.884,10.016 ; v1@169.884,10.016 cw(c170.257,9.643) 170.257,10.17 ccw(c170.257,9.643) v1@169.884,10.016 ; v1@169.884,10.684 ccw(c170.668,11.468) 170.668,10.36 cw(c170.668,11.468) v1@169.884,10.684 ; v1@169.884,10.684 ccw(c170.306,11.106) 170.306,10.51 cw(c170.306,11.106) v1@169.884,10.684 ; 170.88,9.88 cw(c170.88,10.816) 169.996,10.507 ccw(c170.88,10.816) 170.88,9.88 ; 170.89,10.04 cw(c170.89,11.105) 169.962,10.582 ccw(c170.89,11.105) 170.89,10.04 ; 171.1,10.17 cw(c171.1,11.863) 169.888,10.68 ccw(c171.1,11.863) 171.1,10.17 ; 171.59,10.8 ccw(c171.59,8.557) 169.905,10.038 cw(c171.59,8.557) 171.59,10.8 ; v1@169.517,10.338 ccw(c170.163,10.565) 170.163,9.88 cw(c170.163,10.565) v1@169.517,10.338 ; v1@169.524,10.373 cw(c170.467,9.544) 170.467,10.8 ccw(c170.467,9.544) v1@169.524,10.373 ; v1@169.525,10.375 cw(c170.214,9.686) 170.214,10.66 ccw(c170.214,9.686) v1@169.525,10.375 ; v1@169.707,10.503 ccw(c170.497,11.274) 170.497,10.17 cw(c170.497,11.274) v1@169.707,10.503 ; v1@169.715,10.205 cw(c171.029,9.051) 171.029,10.8 ccw(c171.029,9.051) v1@169.715,10.205 ; v1@169.741,10.458 ccw(c170.455,10.86) 170.455,10.04 cw(c170.455,10.86) v1@169.741,10.458 ; v1@169.757,10.422 ccw(c170.522,10.691) 170.522,9.88 cw(c170.522,10.691) v1@169.757,10.422
  Carbon Ink Layer w1.2: v1@163.95,10.35 163.96,10.36 v1@169.53,10.36
  other v1: 169.55,10.35 164,10.4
